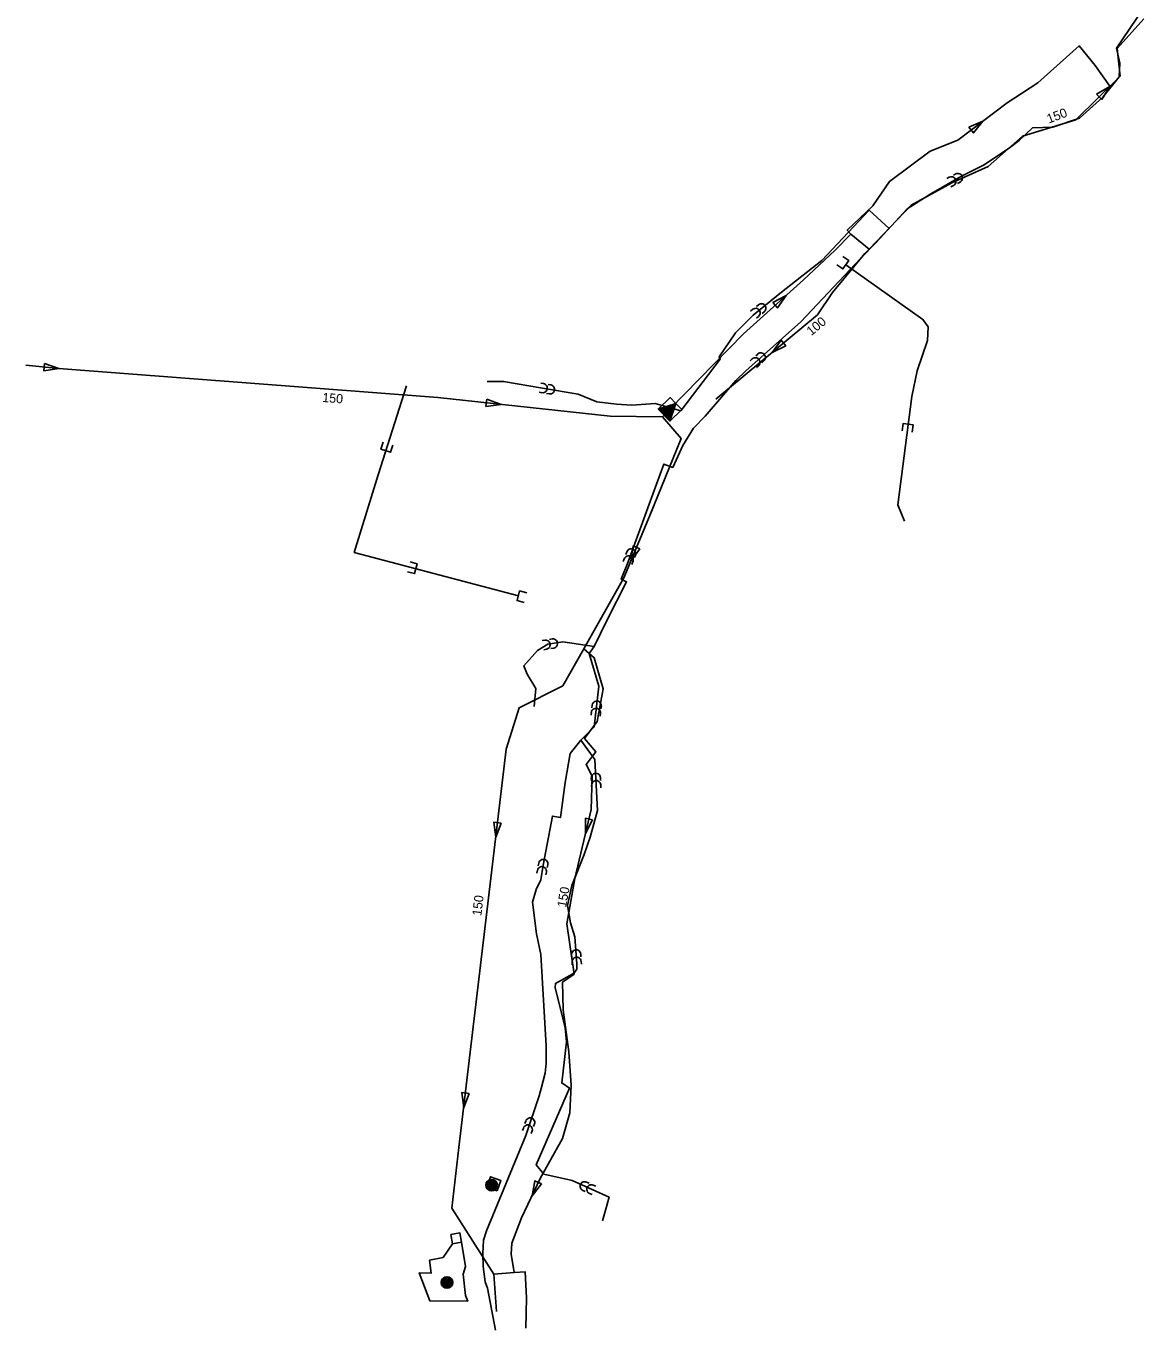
# Model space of a CAD drawing. Extents: x -545007 to -535309, y -1042871 to -1037511.
# Drawn here: x -544148 to -542936, y -1041564 to -1040154 of the extents above; entities that cross this region are included whole.
import ezdxf

# ---------------------------------------------------------------- set-up
doc = ezdxf.new("R2010")
doc.units = 0
for name, color, linetype in [('Vrstva 12', 7, 'Continuous'), ('Vrstva 3', 7, 'Continuous'), ('Vrstva 32', 7, 'Continuous'), ('Vrstva 33', 7, 'Continuous'), ('Vrstva 55', 7, 'Continuous'), ('Vrstva 56', 7, 'Continuous'), ('Vrstva 7', 7, 'Continuous')]:
    doc.layers.add(name, color=color, linetype=linetype)

msp = doc.modelspace()

# ---------------------------------------------------------------- linework, layer by layer
at = {"layer": 'Vrstva 12'}
msp.add_lwpolyline([(-543462.6, -1040569.2), (-543449.6, -1040556.6), (-543443.3, -1040563.1), (-543437, -1040569.5), (-543450, -1040582.1)], dxfattribs=at)
for points in [[(-543462.6, -1040569.2), (-543443.3, -1040563.1), (-543450, -1040582.1)], [(-543461.1, -1040569.5), (-543444.6, -1040564.3), (-543450.3, -1040580.7)], [(-543459.6, -1040569.9), (-543445.9, -1040565.6), (-543450.6, -1040579.2)], [(-543458.1, -1040570.3), (-543447.1, -1040566.8), (-543451, -1040577.7)], [(-543456.7, -1040570.7), (-543448.4, -1040568), (-543451.3, -1040576.2)], [(-543455.2, -1040571), (-543449.7, -1040569.3), (-543451.6, -1040574.7)], [(-543453.7, -1040571.4), (-543451, -1040570.5), (-543451.9, -1040573.2)]]:
    msp.add_lwpolyline(points, close=True, dxfattribs=at)
at = {"layer": 'Vrstva 3'}
for points in [[(-544148.2, -1040521.5), (-544112.6, -1040525.3), (-543701.4, -1040556.7), (-543514.8, -1040576.8), (-543457.8, -1040577.6), (-543449.8, -1040569.4), (-543370.1, -1040487.6), (-543305, -1040428.9), (-543270.5, -1040396.9), (-543253.5, -1040379.2), (-543233.7, -1040395.5), (-543188.3, -1040347.8), (-543144.1, -1040323.7), (-543104.6, -1040306), (-543067.6, -1040273), (-543009.7, -1040255.3), (-542961.4, -1040207.9), (-542964.6, -1040178.1), (-542935.7, -1040145.9)], [(-543253.5, -1040379.2), (-543257.5, -1040375), (-543229.6, -1040348.5), (-543211.8, -1040322.1), (-543167.4, -1040289.3), (-543137.6, -1040277.3), (-543083.9, -1040236.9), (-543050.9, -1040215.1), (-543006, -1040174.9), (-542988.7, -1040196.3), (-542972.6, -1040218.8)], [(-543233.7, -1040395.5), (-543238.3, -1040400.4), (-543273.6, -1040442.7), (-543289.7, -1040466.8), (-543399.9, -1040558.3)], [(-543457.8, -1040577.6), (-543437.7, -1040600.9), (-543471.5, -1040684.6), (-543499.7, -1040752.1), (-543543.2, -1040829.3), (-543566, -1040869.5), (-543613.2, -1040893.2), (-543627.4, -1040938), (-543678.7, -1041370.4), (-543686.5, -1041436.3), (-543640.9, -1041507.7), (-543618.9, -1041506.1), (-543606.8, -1041505.3), (-543605.2, -1041533.4), (-543606, -1041566.4)], [(-543543.2, -1040829.3), (-543531.9, -1040839), (-543522.3, -1040872.7), (-543528.7, -1040908.1), (-543542.4, -1040926.6), (-543530.3, -1040941.1), (-543540.8, -1040954.8), (-543534.3, -1040967.6), (-543535.1, -1041003.7), (-543552.8, -1041078.4), (-543561.7, -1041127.5), (-543553.6, -1041182.2), (-543566.5, -1041191), (-543565.7, -1041220.8), (-543559.3, -1041266.6), (-543556.9, -1041302.8), (-543558.5, -1041332.6), (-543566.5, -1041360.7), (-543590.7, -1041404.1), (-543610.8, -1041446.7), (-543621.2, -1041474.1), (-543622.1, -1041486), (-543618.9, -1041506.1)], [(-543640.9, -1041507.7), (-543637.9, -1041548.3)]]:
    msp.add_lwpolyline(points, dxfattribs=at)
for points in [[(-542987, -1040227.4), (-542981.4, -1040233.1), (-542972.8, -1040219)], [(-543125.5, -1040263.2), (-543120.7, -1040269.6), (-543110.4, -1040256.8)], [(-543338.3, -1040453.5), (-543333, -1040459.4), (-543323.7, -1040445.8)], [(-543324.1, -1040500.6), (-543329.2, -1040494.4), (-543338.9, -1040507.7)], [(-544128, -1040519.6), (-544128.9, -1040527.6), (-544112.6, -1040525.3)], [(-543648.5, -1040558.4), (-543649.3, -1040566.3), (-543633, -1040564.1)], [(-543482.3, -1040720.8), (-543489.7, -1040717.7), (-543492.1, -1040734.1)], [(-543632.9, -1041018.4), (-543640.8, -1041017.4), (-543638.8, -1041033.8)], [(-543533.7, -1041014.9), (-543541.5, -1041013.1), (-543541.3, -1041029.5)], [(-543667.7, -1041311.7), (-543675.6, -1041310.7), (-543673.5, -1041327.1)], [(-543589, -1041409.9), (-543596.2, -1041406.5), (-543599.4, -1041422.7)]]:
    msp.add_lwpolyline(points, close=True, dxfattribs=at)
at = {"layer": 'Vrstva 32'}
for p, q in [((-543146.9, -1040317.6), (-543149.5, -1040319)), ((-543139.7, -1040314), (-543142.4, -1040315.4)), ((-543135.2, -1040322.9), (-543137.9, -1040324.3)), ((-543142.3, -1040326.5), (-543145, -1040327.9)), ((-543360, -1040460.9), (-543362.4, -1040462.8)), ((-543353.8, -1040455.9), (-543356.1, -1040457.8)), ((-543347.5, -1040463.7), (-543349.9, -1040465.6)), ((-543353.7, -1040468.7), (-543356.1, -1040470.6)), ((-543354.5, -1040509.4), (-543356.7, -1040511.4)), ((-543360.5, -1040514.7), (-543362.7, -1040516.7)), ((-543353.9, -1040522.2), (-543356.1, -1040524.2)), ((-543347.9, -1040516.9), (-543350.1, -1040518.9)), ((-543588.6, -1040551.4), (-543591.6, -1040550.9)), ((-543586.9, -1040541.5), (-543589.9, -1040541)), ((-543580.7, -1040552.7), (-543583.7, -1040552.2)), ((-543579, -1040542.9), (-543582, -1040542.4)), ((-543499.3, -1040731.6), (-543500.4, -1040734.4)), ((-543496.6, -1040724.1), (-543497.6, -1040726.9)), ((-543489.9, -1040735), (-543491, -1040737.8)), ((-543487.2, -1040727.5), (-543488.2, -1040730.3)), ((-543585.5, -1040819.9), (-543588.4, -1040820.4)), ((-543577.6, -1040818.6), (-543580.5, -1040819.1)), ((-543583.8, -1040829.8), (-543586.7, -1040830.3)), ((-543575.9, -1040828.4), (-543578.9, -1040828.9)), ((-543534.2, -1040890.3), (-543534.5, -1040893.3)), ((-543535, -1040898.3), (-543535.4, -1040901.3)), ((-543525.1, -1040899.4), (-543525.4, -1040902.3)), ((-543524.2, -1040891.4), (-543524.6, -1040894.4)), ((-543535.1, -1040969.5), (-543535, -1040972.5)), ((-543525.1, -1040969), (-543525, -1040972)), ((-543534.7, -1040977.5), (-543534.6, -1040980.5)), ((-543524.8, -1040977), (-543524.6, -1040980)), ((-543593.5, -1041069.6), (-543594.1, -1041072.6)), ((-543592, -1041061.8), (-543592.6, -1041064.7)), ((-543583.7, -1041071.5), (-543584.3, -1041074.5)), ((-543582.2, -1041063.7), (-543582.8, -1041066.6)), ((-543556.5, -1041161.1), (-543556.3, -1041164.1)), ((-543556, -1041169.1), (-543555.7, -1041172.1)), ((-543546.5, -1041160.4), (-543546.3, -1041163.4)), ((-543546, -1041168.4), (-543545.8, -1041171.4)), ((-543606.1, -1041341.6), (-543607.1, -1041344.4)), ((-543608.7, -1041349.2), (-543609.7, -1041352)), ((-543599.2, -1041352.4), (-543600.2, -1041355.2)), ((-543596.7, -1041344.8), (-543597.6, -1041347.7)), ((-543540.3, -1041407.9), (-543537.5, -1041409.1)), ((-543533, -1041411.1), (-543530.2, -1041412.4)), ((-543544.4, -1041417), (-543541.6, -1041418.2)), ((-543537.1, -1041420.3), (-543534.3, -1041421.5))]:
    msp.add_line(p, q, dxfattribs=at)
for points in [[(-542936.4, -1040134.9), (-542965.5, -1040177.5), (-542962, -1040193.7), (-542962.7, -1040208.6), (-542980.2, -1040230.6), (-543005.5, -1040253.5), (-543034.5, -1040263.4), (-543056.7, -1040264.1), (-543070.9, -1040277.7), (-543081.7, -1040285.7), (-543109, -1040304.1), (-543133.6, -1040316.5), (-543166.9, -1040335.6), (-543192.5, -1040351.8), (-543226.6, -1040388.7), (-543242.9, -1040405.4), (-543307.7, -1040474.6), (-543367.6, -1040527.6), (-543378.3, -1040538), (-543411.6, -1040576.8), (-543424.1, -1040589.7), (-543435.9, -1040608.8), (-543446.6, -1040632.5), (-543456.4, -1040628.9), (-543472.3, -1040672.2), (-543495.2, -1040734.9), (-543502.8, -1040753.6), (-543496.9, -1040756.7), (-543518.2, -1040798.5), (-543531.8, -1040826.9), (-543537.3, -1040834.5), (-543526.9, -1040869.8), (-543531.8, -1040914.1), (-543546.6, -1040928.3), (-543531.1, -1040949.5), (-543528.5, -1041004.7), (-543536.4, -1041033.8), (-543542.7, -1041052.5), (-543556.2, -1041086.1)], [(-543212.2, -1040373.2), (-543233.6, -1040353.2), (-543284.9, -1040407.9), (-543328.9, -1040442.2), (-543359.7, -1040467.1), (-543378.8, -1040486.5), (-543396.4, -1040512.5), (-543395.4, -1040514.9), (-543438, -1040571), (-543466, -1040563), (-543491, -1040564.8), (-543507.9, -1040563.7), (-543529.1, -1040561.3), (-543549.5, -1040553), (-543587.9, -1040546.4), (-543630.2, -1040539.1), (-543647.9, -1040539.1)], [(-543531.8, -1040826.9), (-543566, -1040821.7), (-543582.3, -1040824.4), (-543593.4, -1040831), (-543608.3, -1040847.6), (-543604.5, -1040856.7), (-543595.1, -1040872.2), (-543596.9, -1040892)], [(-543546.6, -1040928.3), (-543557.9, -1040942.7), (-543563.4, -1040974.2), (-543568.6, -1041012.3), (-543577.2, -1041010.8), (-543587.3, -1041063.9)], [(-543587.3, -1041063.9), (-543590, -1041080), (-543594.9, -1041090.3), (-543599, -1041104.2), (-543594.5, -1041138.5), (-543590, -1041161), (-543584, -1041259.9), (-543584, -1041278.9), (-543585.3, -1041289.7), (-543589.5, -1041306.3), (-543591.6, -1041314.3), (-543606.1, -1041357.2), (-543648.6, -1041460.9), (-543652, -1041471), (-543652.7, -1041485.2), (-543652.2, -1041499.6), (-543650.1, -1041516.2), (-543647.7, -1041522.8), (-543639, -1041568.5)], [(-543556.2, -1041086.1), (-543561, -1041107.6), (-543557.6, -1041126.6), (-543552.9, -1041141.7), (-543550.8, -1041171.1), (-543550.8, -1041177), (-543553.2, -1041180.5), (-543555, -1041181.9), (-543574, -1041192.3), (-543574.3, -1041196.8), (-543563.6, -1041240.4), (-543561.9, -1041255.6), (-543567.1, -1041300.3), (-543558.8, -1041305.9), (-543594.8, -1041389), (-543586.5, -1041399.4), (-543556, -1041406.3), (-543515.8, -1041424.3), (-543522.8, -1041449.9)]]:
    msp.add_lwpolyline(points, dxfattribs=at)
for centre, start, end in [((-543144.6, -1040322.1), 296.8903, 116.8914), ((-543137.5, -1040318.5), 296.8903, 116.8914), ((-543356.9, -1040464.8), 308.9803, 128.9814), ((-543350.7, -1040459.8), 308.9803, 128.9814), ((-543351.2, -1040513.1), 311.4878, 131.4889), ((-543357.2, -1040518.4), 311.4878, 131.4889), ((-543587.8, -1040546.4), 260.2865, 80.2876), ((-543579.9, -1040547.8), 260.2865, 80.2876), ((-543491.9, -1040725.8), 339.9655, 159.9666), ((-543494.6, -1040733.3), 339.9655, 159.9666), ((-543584.6, -1040824.8), 279.6563, 99.6573), ((-543576.7, -1040823.5), 279.6563, 99.6573), ((-543529.2, -1040890.9), 353.7563, 173.7574), ((-543530.1, -1040898.8), 353.7563, 173.7574), ((-543530.1, -1040969.3), 2.6948, 182.6958), ((-543529.8, -1040977.2), 2.6948, 182.6958), ((-543587.1, -1041062.7), 349.1421, 169.1432), ((-543588.6, -1041070.6), 349.1421, 169.1432), ((-543551.5, -1041160.8), 4.0414, 184.0424), ((-543551, -1041168.8), 4.0414, 184.0424), ((-543601.4, -1041343.2), 341.2813, 161.2824), ((-543604, -1041350.8), 341.2813, 161.2824), ((-543542.3, -1041412.4), 65.8512, 245.8523), ((-543535, -1041415.7), 65.8512, 245.8523)]:
    msp.add_arc(centre, 5, start, end, dxfattribs=at)
at = {"layer": 'Vrstva 33'}
for points in [[(-543268.7, -1040412.5), (-543262.2, -1040417.1), (-543255.9, -1040408.1), (-543262.4, -1040403.5)], [(-543195.5, -1040690.7), (-543202.7, -1040673.2), (-543187.6, -1040555.5), (-543181.7, -1040527.6), (-543170.4, -1040494.6), (-543169.9, -1040480.1), (-543175.4, -1040471.9), (-543259, -1040412.6)], [(-543614.2, -1040771.7), (-543792.2, -1040724.7), (-543766.4, -1040640.6), (-543735.5, -1040544)], [(-543187, -1040594.2), (-543186, -1040586.3), (-543196.9, -1040584.9), (-543197.9, -1040592.9)], [(-543760.8, -1040605), (-543763.2, -1040612.6), (-543752.8, -1040616), (-543750.3, -1040608.4)], [(-543734.6, -1040745.6), (-543726.8, -1040747.6), (-543724, -1040737), (-543731.7, -1040735)], [(-543605, -1040768.4), (-543612.8, -1040766.4), (-543615.6, -1040777), (-543607.8, -1040779.1)]]:
    msp.add_lwpolyline(points, dxfattribs=at)
at = {"layer": 'Vrstva 55'}
for points in [[(-543637.2, -1041417.4), (-543633.1, -1041406.1), (-543644.4, -1041402), (-543648.5, -1041413.3), (-543637.2, -1041417.4)], [(-543685.6, -1041474.7), (-543675.7, -1041472.9), (-543677.6, -1041463), (-543687.4, -1041464.9), (-543685.6, -1041474.7)]]:
    msp.add_lwpolyline(points, dxfattribs=at)
at = {"layer": 'Vrstva 56'}
msp.add_lwpolyline([(-543674.2, -1041507.7), (-543671.7, -1041499.3), (-543675.7, -1041472.9), (-543677.6, -1041463), (-543687.4, -1041464.9), (-543685.6, -1041474.7), (-543695.8, -1041489.8), (-543710.6, -1041492.7), (-543708.9, -1041506.8), (-543721.7, -1041506.3), (-543710.2, -1041536.8), (-543669.1, -1041537.2), (-543671.6, -1041530.8), (-543674.2, -1041507.7)], dxfattribs=at)
at = {"layer": 'Vrstva 7'}
for centre, radius in [((-543643.2, -1041411.2), 6.3), ((-543643.2, -1041411.2), 5.3), ((-543643.2, -1041411.2), 4.3), ((-543643.2, -1041411.2), 3.3), ((-543643.2, -1041411.2), 2.3), ((-543643.2, -1041411.2), 1.3), ((-543643.2, -1041411.2), 0.3), ((-543691.6, -1041516.8), 6.3), ((-543691.6, -1041516.8), 5.3), ((-543691.6, -1041516.8), 4.3), ((-543691.6, -1041516.8), 3.3), ((-543691.6, -1041516.8), 2.3), ((-543691.6, -1041516.8), 1.3), ((-543691.6, -1041516.8), 0.3)]:
    msp.add_circle(centre, radius, dxfattribs=at)

# ---------------------------------------------------------------- texts
at = {"layer": 'Vrstva 3'}
for s, rotation, p in [('150', 20.8222, (-543038.8, -1040259.4)), ('100', 39.7011, (-543296.5, -1040490.1)), ('150', 355.6377, (-543827, -1040561.4)), ('150', 79.7731, (-543562.5, -1041110.4)), ('150', 83.2396, (-543654.4, -1041119.4))]:
    msp.add_text(s, height=10, rotation=rotation, dxfattribs=at).set_placement(p)

doc.saveas('drawing.dxf')
